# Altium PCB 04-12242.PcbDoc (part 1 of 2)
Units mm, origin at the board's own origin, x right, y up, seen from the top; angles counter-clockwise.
Board outline 90 x 78 mm, 2 copper layers (Top Layer, Bottom Layer), stack 1.57 mm thick; 64 components, 48 nets, 276 pads, 503 vias.
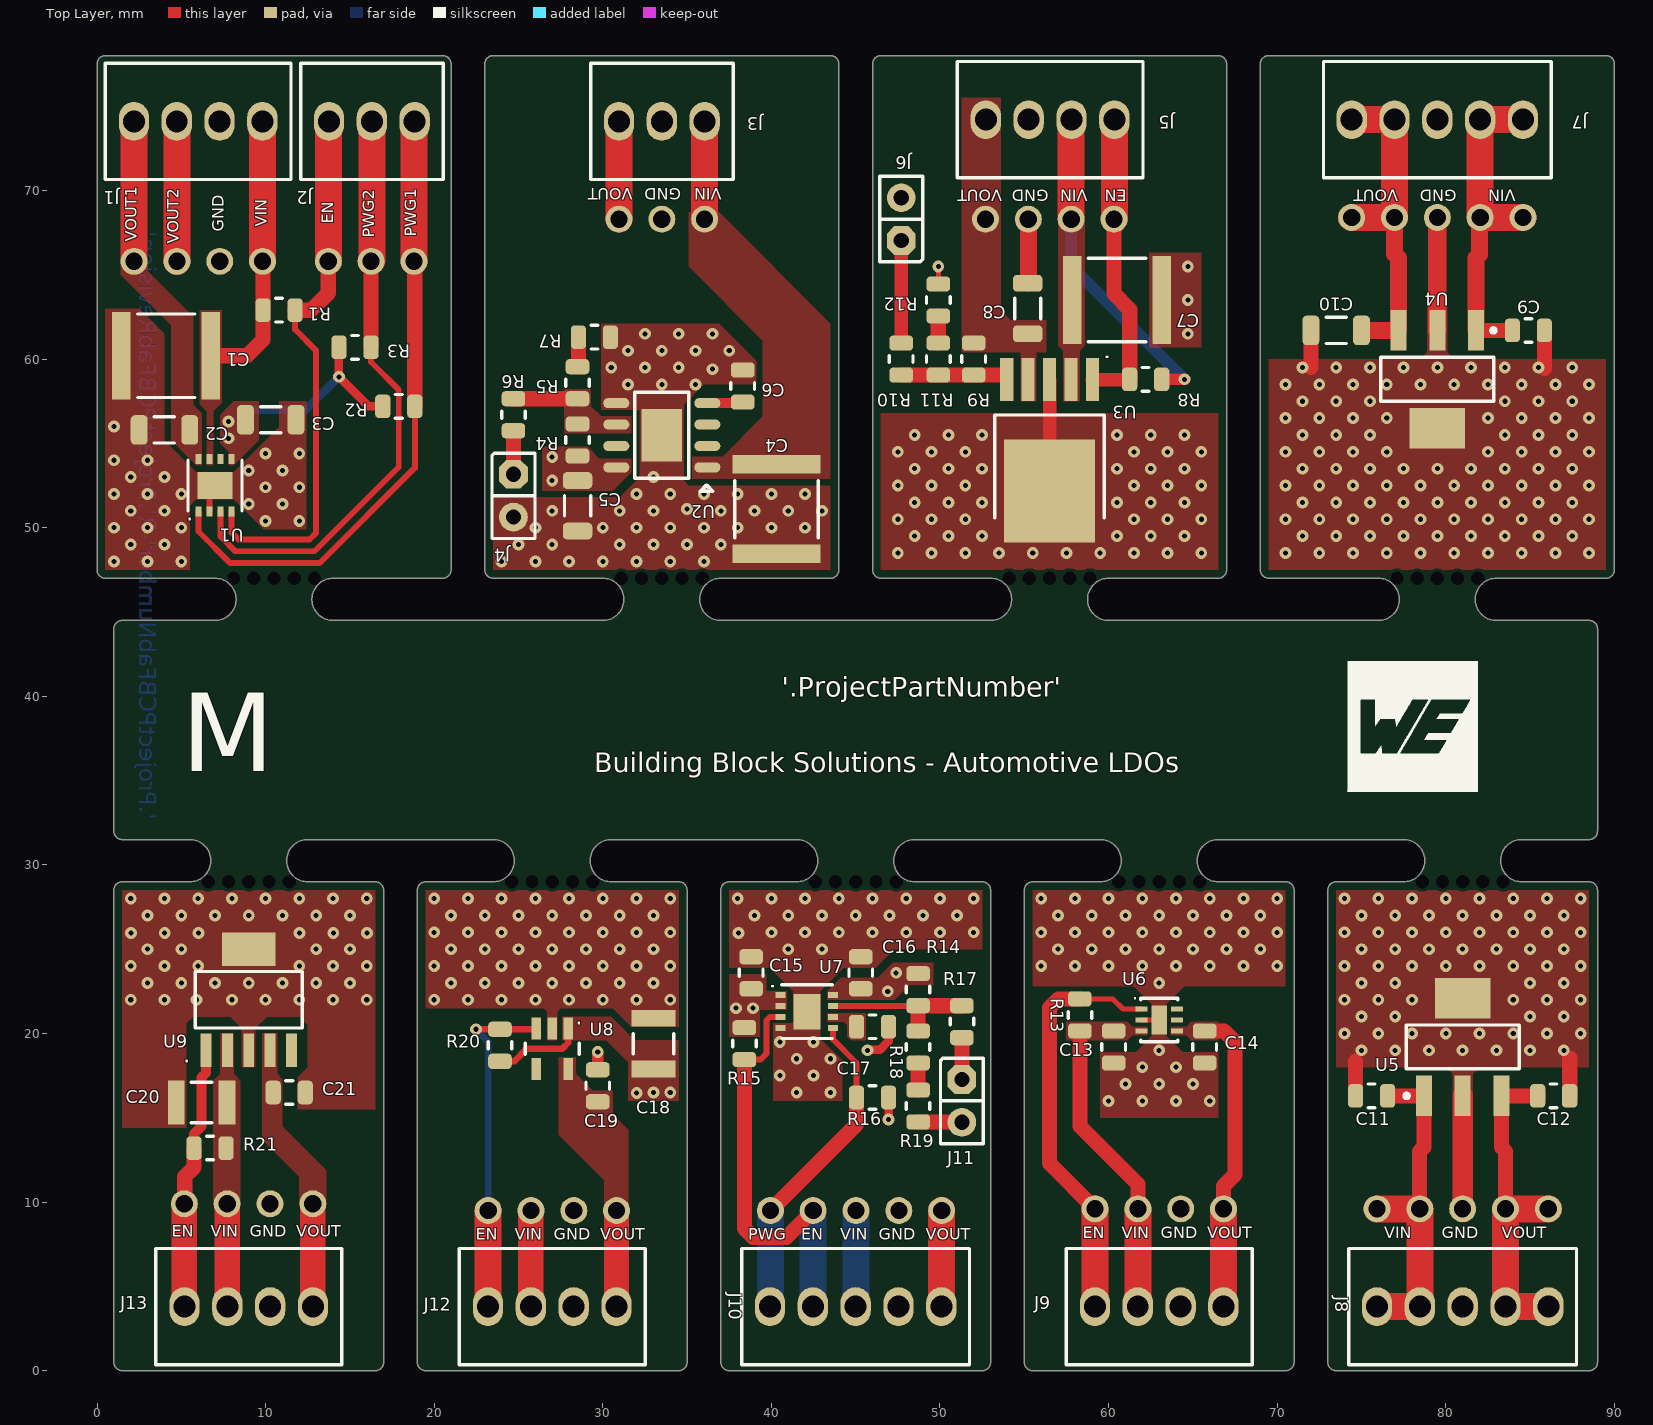
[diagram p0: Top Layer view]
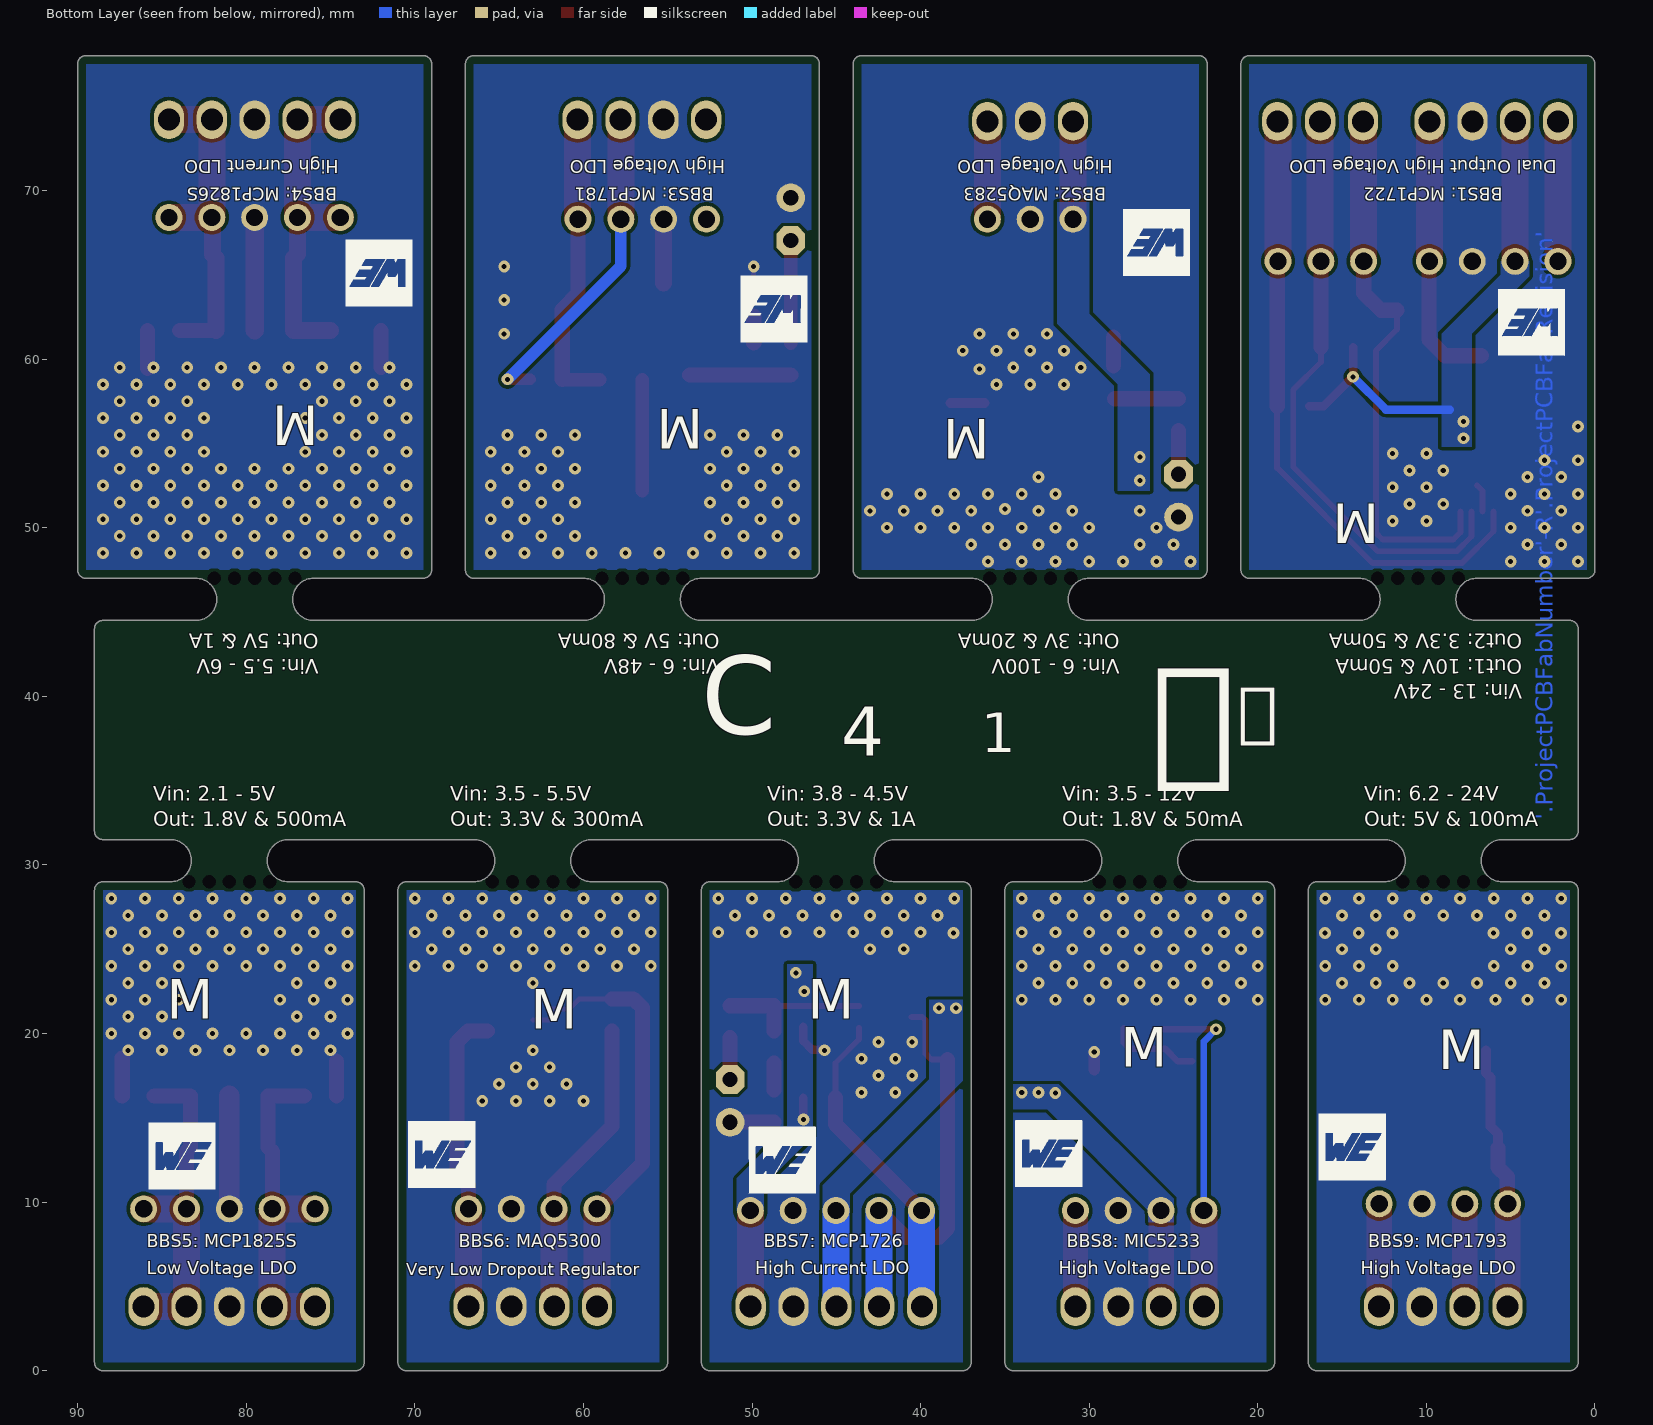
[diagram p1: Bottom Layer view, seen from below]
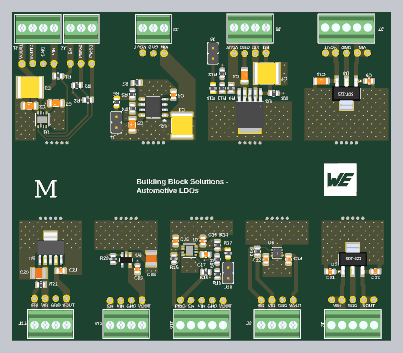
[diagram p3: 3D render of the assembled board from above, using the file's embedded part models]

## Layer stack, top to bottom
Top Solder: solder mask 0.01, Solder Resist, Dk 3.5
Top Layer: signal copper 0.035
Dielectric1: core 1.5, FR-4, Dk 4.8
Bottom Layer: signal copper 0.035
Bottom Solder: solder mask 0.01, Solder Resist, Dk 3.5

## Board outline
1.5,0 16.5,0 ccw(c16.5,0.5) 17,0.5 17,28.5 ccw(c16.5,28.5) 16.5,29 12.5,29 cw(c12.5,30.25) 12.5,31.5 23.5,31.5 cw(c23.5,30.25) 23.5,29 19.5,29 ccw(c19.5,28.5) 19,28.5 19,0.497 19,0.5 ccw(c19.5,0.5) 19.5,0 34.5,0 ccw(c34.5,0.5) 35,0.5 35,28.5 ccw(c34.5,28.5) 34.5,29 30.5,29 cw(c30.5,30.25) 30.5,31.5 41.5,31.5 cw(c41.5,30.25) 41.5,29 37.5,29 ccw(c37.5,28.5) 37,28.5 37,0.5 ccw(c37.5,0.5) 37.5,0 52.5,0 ccw(c52.5,0.5) 53,0.5 53,28.5 ccw(c52.5,28.5) 52.5,29 48.5,29 cw(c48.5,30.25) 48.5,31.5 59.5,31.5 cw(c59.5,30.25) 59.5,29 55.5,29 ccw(c55.5,28.5) 55,28.5 55,0.5 ccw(c55.5,0.5) 55.5,0 70.5,0 ccw(c70.5,0.5) 71,0.5 71,0.496 71,28.5 ccw(c70.5,28.5) 70.5,29 66.5,29 cw(c66.5,30.25) 66.5,31.5 77.5,31.5 cw(c77.5,30.25) 77.5,29 73.5,29 ccw(c73.5,28.5) 73,28.5 73,0.5 ccw(c73.5,0.5) 73.5,0 88.5,0 ccw(c88.5,0.5) 89,0.5 89,0.495 89,28.5 ccw(c88.5,28.5) 88.5,29 84.5,29 cw(c84.5,30.25) 84.5,31.5 88.5,31.5 ccw(c88.5,32) 89,32 89,44 ccw(c88.5,44) 88.5,44.5 83,44.5 cw(c83,45.75) 83,47 89.5,47 ccw(c89.5,47.5) 90,47.5 90,77.5 ccw(c89.5,77.5) 89.5,78 69.5,78 ccw(c69.5,77.5) 69,77.5 69,47.5 ccw(c69.5,47.5) 69.5,47 76,47 cw(c76,45.75) 76,44.5 60,44.5 cw(c60,45.75) 60,47 66.5,47 ccw(c66.5,47.5) 67,47.5 67,77.5 ccw(c66.5,77.5) 66.5,78 46.5,78 ccw(c46.5,77.5) 46,77.5 46,47.5 ccw(c46.5,47.5) 46.5,47 53,47 cw(c53,45.75) 53,44.5 37,44.5 cw(c37,45.75) 37,47 43.5,47 ccw(c43.5,47.5) 44,47.5 44,77.5 ccw(c43.5,77.5) 43.5,78 23.5,78 ccw(c23.5,77.5) 23,77.5 23,47.5 ccw(c23.5,47.5) 23.5,47 30,47 cw(c30,45.75) 30,44.5 14,44.5 cw(c14,45.75) 14,47 20.5,47 ccw(c20.5,47.5) 21,47.5 21,77.5 ccw(c20.5,77.5) 20.5,78 0.5,78 ccw(c0.5,77.5) 0,77.5 0,47.5 ccw(c0.5,47.5) 0.5,47 7,47 cw(c7,45.75) 7,44.5 1.5,44.5 ccw(c1.5,44) 1,44 1,32 ccw(c1.5,32) 1.5,31.5 5.5,31.5 cw(c5.5,30.25) 5.5,29 1.5,29 ccw(c1.5,28.5) 1,28.5 1,0.496 1,0.5 ccw(c1.5,0.5)

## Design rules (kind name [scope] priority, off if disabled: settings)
AcuteAngle [All] p1: minimum=9.00000000000000E+0001 checktracksonly=TRUE
BoardOutlineClearance "Ignore Title Block elements" [InNamedUnion('Title Block')] p1: gap=0 ignorepadtopadclearanceinfootprint=FALSE
BoardOutlineClearance BoardOutlineClearance_Overlay [OnLayer('Top Overlay','Bottom Overlay')] p2: gap=0.2 ignorepadtopadclearanceinfootprint=FALSE
BoardOutlineClearance [All] p3: gap=0.5 ignorepadtopadclearanceinfootprint=FALSE
Clearance "Net to Polygon 0.5mm" [InNet('your net here') vs (IsRegion)] p1: gap=0.2 ignorepadtopadclearanceinfootprint=FALSE
Clearance "Poly 0.3mm" [(IsRegion)] p2: gap=0.2 ignorepadtopadclearanceinfootprint=FALSE
Clearance [All] p3: gap=0.2 ignorepadtopadclearanceinfootprint=TRUE
ComponentClearance ComponentClearance_ignore [HasFootprint('NET_TIE_0.5mm')] p1: gap=0 collisioncheckmode=3 verticalgap=0 showdistances=FALSE
ComponentClearance [All] p2: gap=0.2 collisioncheckmode=3 verticalgap=0.2 showdistances=FALSE
DiffPairsRouting [All] p1: maxlimit=0.25 minlimit=0.25 mostfreqgap=0.25 toplayer_minwidth=0.25 toplayer_maxwidth=0.25 toplayer_prefwidth=0.25 bottomlayer_minwidth=0.25 bottomlayer_maxwidth=0.25 bottomlayer_prefwidth=0.25 maxuncoupledlength=12.7
FabricationTestPointUsage TestPointUsage [All] p1: valid=0 allowmultiple=FALSE
FabricationTestpoint Testpoint [All] p1: side=3 testpointundercomponent=TRUE minsize=1.016 maxsize=2.54 preferedsize=1.524 minholesize=0 maxholesize=1.016 preferedholesize=0.813 testpointgrid=0.025 allowsidetop=TRUE allowsidebottom=TRUE usegrid=TRUE gridtolerance=0
HoleSize [All] p1: absolutevalues=TRUE maxlimit=6 minlimit=0.25 maxpercent=80.000 minpercent=20.000
HoleToHoleClearance [All] p1: gap=0.3 allowstackedmicrovias=FALSE
MinimumAnnularRing [All] p1: minimumring=0.15
MinimumSolderMaskSliver [All] p1: minsoldermaskwidth=0.1
PasteMaskExpansion PasteMaskExpansion_DNP [IsPad AND HasCompParameterValue('Populated','DNP')] p1: expansion=-5
PasteMaskExpansion [All] p2: expansion=0
PlaneClearance PlaneClearance_pads [IsPad] p1: clearance=0.3
PlaneClearance PlaneClearance_drill [IsObjectKind('Hole')] p2: clearance=0.4
PlaneConnect PlaneConnect_full [IsVia] p1: planeconnectstyle=Direct reliefexpansion=0.5 reliefentries=4 reliefconductorwidth=0.3 reliefairgap=0.3
PlaneConnect [All] p2: planeconnectstyle=Relief reliefexpansion=0.3 reliefentries=4 reliefconductorwidth=0.25 reliefairgap=0.25
PolygonConnect PolygonConnect_0.7 [IsNamedPolygon('0.7mm') vs (InPadClass('All Pads'))] p1: connectstyle=Relief reliefconductorwidth=0.7 reliefentries=4 polygonreliefangle="90 Angle" airgapwidth=0.25
PolygonConnect PolygonConnect_0.5 [IsNamedPolygon('0.5mm') vs (InPadClass('All Pads'))] p2: connectstyle=Relief reliefconductorwidth=0.5 reliefentries=4 polygonreliefangle="90 Angle" airgapwidth=0.25
PolygonConnect PolygonConnect_full [All vs IsVia or IsNamedPolygon('full')] p3: connectstyle=Direct reliefconductorwidth=0 reliefentries=4 polygonreliefangle="90 Angle" airgapwidth=0.254
PolygonConnect [All] p4: connectstyle=Relief reliefconductorwidth=0.3 reliefentries=4 polygonreliefangle="90 Angle" airgapwidth=0.25
RoutingCorners [All] p1: cornerstyle=45-Degree minsetback=2.5 maxsetback=2.5
RoutingVias [All] p1: holewidth=0.4 width=0.8 viastyle="Through Hole" minholewidth=0.3 minwidth=0.7 maxholewidth=1.6 maxwidth=2.5
SMDToCorner [All] p1: distance=39370
ShortCircuit [IsNet] p1: allowed=FALSE
SilkToSilkClearance [All] p1: silktosilkclearance=0.15
SilkToSolderMaskClearance SilkscreenOverComponentPads [IsPad] p1: minsilkscreentomaskgap=0.2 clearancetoexposedcopper=TRUE
SolderMaskExpansion SolderMaskExpansion_Component_Via [IsComponentVia] p1: expansion=0.075 istentingtop=FALSE soldermaskfromhole=TRUE
SolderMaskExpansion [All] p2: expansion=0.1 istentingtop=FALSE
SupplyNets "Schematic Supply Nets_1" [InNet('GND_2')] p1: voltage=0.000
SupplyNets "Schematic Supply Nets_8" [InNet('GND_9')] p2: voltage=0.000
SupplyNets "Schematic Supply Nets_4" [InNet('GND_8')] p3: voltage=0.000
SupplyNets "Schematic Supply Nets_7" [InNet('GND_3')] p4: voltage=0.000
SupplyNets "Schematic Supply Nets_6" [InNet('GND_4')] p5: voltage=0.000
SupplyNets "Schematic Supply Nets_5" [InNet('GND_7')] p6: voltage=0.000
SupplyNets "Schematic Supply Nets_3" [InNet('GND_5')] p7: voltage=0.000
SupplyNets "Schematic Supply Nets_2" [InNet('GND_6')] p8: voltage=0.000
SupplyNets "Schematic Supply Nets" [InNet('GND_1')] p9: voltage=0.000
UnRoutedNet [All] p1: checkbadconnections=TRUE
ViasUnderSMD [All] p1: allowed=FALSE
Width [All] p1: maxlimit=7 minlimit=0.2 preferedwidth=0.25
15 further rules are at their usual default settings.

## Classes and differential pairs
component class MAQ5300_schematic: C13 C14 J9 R13 U6
component class MAQ5283_schematic: C4 C5 C6 J3 J4 R4 R5 R6 R7 U2
component class MCP1825S_schematic: C11 C12 J8 U5
component class MIC5233_schematic: C18 C19 J12 R20 U8
component class MCP1793_schematic: C20 C21 J13 R21 U9
component class MCP1726_schematic: C15 C16 C17 J10 J11 R14 R15 R16 R17 R18 R19 U7
component class MCP1722_schematic: C1 C2 C3 J1 J2 R1 R2 R3 U1
component class MCP1826S_schematic: C9 C10 J7 U4
component class MCP1781_schematic: C7 C8 J5 J6 R8 R9 R10 R11 R12 U3

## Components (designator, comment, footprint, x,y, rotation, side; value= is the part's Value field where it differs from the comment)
C1 "Capacitor NP" CAP_C_2220 4.1,60.2 r0 top value=4.7uF
C2 "Capacitor NP" CAP_C_1206 4,55.8 r0 top value=3.3uF
C3 "Capacitor NP" CAP_C_1206 10.3,56.4 r180 top value=3.3uF
C4 "Capacitor NP" CAP_C_2220 40.3,51.1 r90 top value=1uF
C5 "Capacitor NP" CAP_C_1206 28.5,51.3 r90 top value=10uF
C6 "Capacitor NP" CAP_C_0805 38.3,58.4 r270 top value=0.1uF
C7 "Capacitor NP" CAP_C_2220 60.5,63.5 r180 top value=4.7uF
C8 "Capacitor NP" CAP_C_1206 55.2,63 r270 top value=3.3uF
C9 "Capacitor NP" CAP_C_0805 84.9,61.7 r180 top value=1uF
C10 "Capacitor NP" CAP_C_1206 73.5,61.7 r0 top value=10uF
C11 "Capacitor NP" CAP_C_0805 75.6,16.3 r0 top value=1uF
C12 "Capacitor NP" CAP_C_0805 86.4,16.3 r180 top value=1uF
C13 "Capacitor NP" CAP_C_0805 60.3,19.2 r90 top value=1uF
C14 "Capacitor NP" CAP_C_0805 65.7,19.2 r90 top value=1uF
C15 "Capacitor NP" CAP_C_0805 38.8,23.6 r270 top value=1uF
C16 "Capacitor NP" CAP_C_0805 45.3,23.6 r270 top value=1uF
C17 "Capacitor NP" CAP_C_0805 46,20.4 r180 top value=0.1uF
C18 "Capacitor NP" CAP_C_1210 33,19.4 r270 top value=2.2uF
C19 "Capacitor NP" CAP_C_0805 29.7,16.9 r270 top value=2.2uF
C20 "Capacitor NP" CAP_C_1210 6.2,15.9 r0 top value=2.2uF
C21 "Capacitor NP" CAP_C_0805 11.4,16.5 r180 top value=2.2uF
J1 "Header 1x4" CON_TERMINAL_2.54_1x4_TH_RA_WE 6,74.1 r180 top value="TERMINAL 1x4"
J2 "Header 1x3" CON_TERMINAL_2.54_1x3_TH_RA_WE 16.3,74.1 r180 top value="TERMINAL 1x3"
J3 "Header 1x3" CON_TERMINAL_2.54_1x3_TH_RA_WE 33.5,74.1 r180 top value="TERMINAL 1x3"
J4 "Header 1x2" HDR_M_2.54_1x2 24.7,51.9 r270 top value="HDR-2.54 Male 1x2"
J5 "Header 1x4" CON_TERMINAL_2.54_1x4_TH_RA_WE 56.53,74.2 r180 top value="TERMINAL 1x4"
J6 "Header 1x2" HDR_M_2.54_1x2 47.7,68.3 r90 top value="HDR-2.54 Male 1x2"
J7 "Header 1x5" CON_TERMINAL_2.54_1x5_TH_RA_WE 79.5,74.2 r180 top value="TERMINAL 1x5"
J8 "Header 1x5" CON_TERMINAL_2.54_1x5_TH_RA_WE 81,3.8 r0 top value="TERMINAL 1x5"
J9 "Header 1x4" CON_TERMINAL_2.54_1x4_TH_RA_WE 63,3.8 r0 top value="TERMINAL 1x4"
J10 "Header 1x5" CON_TERMINAL_2.54_1x5_TH_RA_WE 45,3.8 r0 top value="TERMINAL 1x5"
J11 "Header 1x2" HDR_M_2.54_1x2 51.3,16 r270 top value="HDR-2.54 Male 1x2"
J12 "Header 1x4" CON_TERMINAL_2.54_1x4_TH_RA_WE 27,3.8 r0 top value="TERMINAL 1x4"
J13 "Header 1x4" CON_TERMINAL_2.54_1x4_TH_RA_WE 9,3.8 r0 top value="TERMINAL 1x4"
R1 "Resistor" RES_C_0805#1 10.8,62.9 r180 top value=100k
R2 "Resistor" RES_C_0805#1 17.9,57.2 r0 top value=100k
R3 "Resistor" RES_C_0805#1 15.3,60.7 r0 top value=100k
R4 "Resistor" RES_C_0805#1 28.5,55.2 r90 top value=100k
R5 "Resistor" RES_C_0805#1 28.5,58.6 r270 top value=68k
R6 "Resistor" RES_C_0805#2 24.7,56.7 r90 top value=100k
R7 "Resistor" RES_C_0805#1 29.5,61.3 r180 top value=1.3k
R8 "Resistor" RES_C_0805#1 62.2,58.8 r0 top value=100k
R9 "Resistor" RES_C_0805#1 52,60 r270 top value=100k
R10 "Resistor" RES_C_0805#2 47.7,60 r270 top value=100k
R11 "Resistor" RES_C_0805#1 49.9,60 r270 top value=1.8k
R12 "Resistor" RES_C_0805#1 49.9,63.5 r270 top value=30k
R13 "Resistor" RES_C_0805#1 58.3,21.1 r90 top value=100k
R14 "Resistor" RES_C_0805#1 48.7,22.6 r90 top value=100k
R15 "Resistor" RES_C_0805#1 38.4,19.4 r270 top value=100k
R16 "Resistor" RES_C_0805#1 46,16.2 r0 top value=100k
R17 "Resistor" RES_C_0805#2 51.3,20.7 r90 top value=100k
R18 "Resistor" RES_C_0805#1 48.7,19.2 r90 top value=13K
R19 "Resistor" RES_C_0805#1 48.7,15.7 r90 top value=1.2k
R20 "Resistor" RES_C_0805#1 23.9,19.3 r90 top value=100k
R21 "Resistor" RES_C_0805#1 6.7,13.2 r0 top value=100k
U1 "MCP1722_DFN-8_EP" DFN-8_3x3 7,52.513 r0 top value=MCP1722/3.3V/10V
U2 "MAQ5283_SOIC-8" SOIC-8_EP2.41x3.1 33.5,55.483 r180 top value=MAQ5283YME-TRVAO
U3 "MCP1781 SOT-223-5_ADJ" TO-252-5_5pins 56.5,54.6 r180 top value=MCP1781
U4 "MIC39100 SOT-223-3" SOT-223-3 79.5,58.8 r180 top value=MCP1826S/5V
U5 "MIC39100 SOT-223-3" SOT-223-3 81,19.2 r0 top value=MCP1825S/1.8V
U6 "MAQ5300 DFN-6" DFN-6_2x2_EP1.7x0.9 63,20.8 r270 top value=MAQ5300-3.3YML-TRVAO
U7 "MCP172X ADJ DFN-8" DFN-8_3x3 42.1,21.3 r270 top value=MCP1726T-ADJE/MFVAO
U8 "MIC5233 SOT-23-5" SOT-23-5 27,19.1 r180 top value=MIC5233-1.8YM5
U9 "MCP1793T_SOT-223" SOT-223-5 9,22 r0 top value=MCP1793T-5002H/DCVAO

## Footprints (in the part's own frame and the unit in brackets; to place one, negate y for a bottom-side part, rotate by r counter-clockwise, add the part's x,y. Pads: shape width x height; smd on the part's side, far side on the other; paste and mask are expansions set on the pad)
CAP_C_0805 [mm] "Chip Capacitor, 2-Leads, Body 2.0x1.3mm, IPC Medium Density"
  rrect50% 0.9x1.4 smd: 1(-0.95,0) 2(0.95,0)
  silkscreen extent -0.2,-0.7 0.2,0.7, body extent -1,-0.62 1,0.63, height 0.78
CAP_C_1206 [mm] "Chip Capacitor, 2-Leads, Body 3.2x1.6mm, IPC Medium Density"
  rrect50% 1x1.75 smd: 1(-1.5,0) 2(1.5,0)
  silkscreen extent -0.6,-0.77 0.6,0.77, body extent -1.6,-0.8 1.6,0.8, height 1
CAP_C_1210 [mm] "Chip Capacitor, 2-Leads, Body 3.2x2.5mm, IPC Medium Density"
  rect 1x2.6 smd: 1(-1.5,0) 2(1.5,0)
  silkscreen extent -0.6,-1.2 0.6,1.2, body extent -1.6,-1.25 1.6,1.25, height 0.95
CAP_C_2220 [mm] "Chip Capacitor, 2-Leads, Body 5.7x5.0mm, IPC Medium Density"
  rect 1.1x5.2 smd: 1(-2.65,0) 2(2.65,0)
  silkscreen extent -1.7,-2.47 1.7,2.48, body extent -2.85,-2.5 2.85,2.5, height 2.3
CON_TERMINAL_2.54_1x3_TH_RA_WE [mm]
  oval 1.8x2.3 hole 1.3: 1(-2.54,0) 2(0,0) 3(2.54,0)
  silkscreen extent -4.24,-3.45 4.22,3.45, body extent -4.01,-3.25 4.01,3.25, height 8.55
CON_TERMINAL_2.54_1x4_TH_RA_WE [mm]
  oval 1.8x2.3 hole 1.3: 1(-3.81,0) 2(-1.27,0) 3(1.27,0) 4(3.81,0)
  silkscreen extent -5.51,-3.45 5.51,3.45, body extent -5.28,-3.25 5.28,3.25, height 8.55
CON_TERMINAL_2.54_1x5_TH_RA_WE [mm] "CON_TERMINAL_2.54_1x5_TH_RA_WE"
  oval 1.8x2.3 hole 1.3: 1(-5.08,0) 2(-2.54,0) 3(0,0) 4(2.54,0) 5(5.08,0)
  silkscreen extent -6.75,-3.45 6.75,3.45, body extent -6.55,-3.25 6.55,3.25, height 8.55
DFN-6_2x2_EP1.7x0.9 [mm] "DFN, 6-Leads, Body 2.0x2.0mm (max), Pitch 0.65"
  rect 0.3x0.7 smd: 1(-0.65,-1.05) 2(0,-1.05) 3(0.65,-1.05) 4(0.65,1.05) 5(0,1.05) 6(-0.65,1.05)
  rect 1.7x0.9 smd mask+0.05: 7(0,0)
  silkscreen extent -1.3,-1.1 1.3,1.1, body extent -1,-1 1,1, height 0.75
DFN-8_3x3 [mm] "DFN, 8-Leads, Body 3.0x3.0mm (max), Pitch 0.65mm, IPC Medium Density"
  rect 0.35x0.6 smd: 1(-0.975,-1.55) 2(-0.325,-1.55) 3(0.325,-1.55) 4(0.975,-1.55) 5(0.975,1.55) 6(0.325,1.55) 7(-0.325,1.55) 8(-0.975,1.55)
  rect 2.1x1.6 smd: 9(0,0)
  silkscreen extent -1.6,-1.5 1.6,1.5, body extent -1.5,-1.5 1.5,1.5, height 0.6
HDR_M_2.54_1x2 [mm] "Header Male Vertical 2 Way 2.54mm Pitch"
  oct 1.7x1.7 hole 0.9: 1(-1.27,0)
  round 1.7 hole 0.9: 2(1.27,0)
  silkscreen extent -2.52,-1.27 2.54,1.28, body extent -2.54,-1.27 2.54,1.27, height 5.94
RES_C_0805#1 [mm] "Chip Resistor, 2-Leads, Body 2.0x1.3mm, IPC Medium Density"
  rrect50% 0.9x1.4 smd: 1(-0.95,0) 2(0.95,0)
  silkscreen extent -0.2,-0.7 0.2,0.7, body extent -1,-0.63 1,0.63, height 0.78
RES_C_0805#2 [mm] "Chip Resistor, 2-Leads, Body 2.0x1.3mm, IPC Medium Density"
  rrect50% 0.9x1.4 smd paste-1: 1(-0.95,0) 2(0.95,0)
  silkscreen extent -0.2,-0.7 0.2,0.7, body extent -1,-0.63 1,0.63, height 0.78
SOIC-8_EP2.41x3.1 [mm] "SOIC, 8-Leads, Overall 4.9x6mm, Pitch 1.27mm, Exposed Pad 2.41x3.1mm, IPC Medium Density"
  oval 1.55x0.6 smd: 1(-2.7,1.905) 2(-2.7,0.635) 3(-2.7,-0.635) 4(-2.7,-1.905) 5(2.7,-1.905) 6(2.7,-0.635) 7(2.7,0.635) 8(2.7,1.905)
  rect 2.41x3.1 smd: 9(0,0)
  silkscreen extent -3.03,-2.55 1.6,3.32, body extent -3.01,-2.5 3.01,2.5, height 1.75
SOT-23-5 [mm] "SOT-23-5"
  rect 0.55x1.3 smd: 1(-0.95,-1.2) 2(0,-1.2) 3(0.95,-1.2) 4(0.95,1.2) 5(-0.95,1.2)
  silkscreen extent -1.6,-0.33 1.6,0.33, body extent -1.5,-1.25 1.5,1.25, height 1.08
SOT-223-3 [mm] "SOT223-3, 4-Leads, Body 6.7x7.3mm (max), Pitch 2.30mm, IPC Medium Density"
  rect 0.95x2.4 smd: 1(-2.3,-2.9) 2(0,-2.9) 3(2.3,-2.9)
  rect 3.3x2.4 smd: 2(0,2.9)
  silkscreen extent -3.45,-3.02 3.35,1.3, body extent -3.3,-3.55 3.4,3.65, height 1.85
SOT-223-5 [mm] "SOT-223-5, 5-Leads + thermal connected to pin 3, Body 6.5x7.26mm (max), Pitch 1.27mm H=1.65mm"
  rect 0.65x2 smd: 1(-2.54,-3) 2(-1.27,-3) 3(0,-3) 4(1.27,-3) 5(2.54,-3)
  rect 3.2x2 smd: 6(0,3)
  silkscreen extent -3.17,-1.68 3.17,1.68, body extent -3.27,-3.63 3.28,3.63, height 1.8
TO-252-5_5pins [mm]
  rect 0.78x2.56 smd: 1(-2.54,-4.18) 2(-1.27,-4.18) 3(0,-4.18) 4(1.27,-4.18) 5(2.54,-4.18)
  rect 5.4x6.11 smd paste-4: 6(0,2.41)
  silkscreen extent -3.25,-2.08 3.25,4.02, body extent -3.3,-4.96 3.3,5.25, height 2.39

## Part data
C1 C7: library part CAP0569, Manufacturer 1="Wuerth Elektronik", Manufacturer 2=Murata, Manufacturer Part Number 1=885012214003, Manufacturer Part Number 2=GRM55ER72A475KA01L, Operating Temperature="-55C to +125C", Package=2220, Supplier Part Number 1=732-885012214003TR-ND, Temperature Coefficient=X7R, Tolerance=10%, Voltage=100V
C2 C3 C8: library part CAP3265, Manufacturer 1="Wuerth Elektronik", Manufacturer Part Number 1=885012208067, Operating Temperature="-55C to +125C", Package=1206, Supplier Part Number 1=732-7572-2-ND, Temperature Coefficient=X7R, Tolerance=10%, Voltage=25V
C4: library part CAP3266, Manufacturer 1="Wuerth Elektronik", Manufacturer Part Number 1=885342214002, Operating Temperature="-55C to +125C", Package=2220, Supplier Part Number 1=732-885342214002TR-ND, Temperature Coefficient=X7R, Tolerance=10%, Voltage=250V
C5 C10: library part CAP2272, Manufacturer 1="Würth Elektronik", Manufacturer Part Number 1=885012208069, Operating Temperature="-55C to +125C", Package=1206, Supplier Part Number 1=732-7574-1-ND, Temperature Coefficient=X7R, Tolerance=10%, Voltage=25V
C6 C17: library part CAP3267, Manufacturer 1="Wuerth Elektronik", Manufacturer Part Number 1=885012207072, Operating Temperature="-55C to +125C", Package=0805, Supplier Part Number 1=732-8061-2-ND, Temperature Coefficient=X7R, Tolerance=10%, Voltage=25V
C9 C11 C12 C13 C14 C15 C16: library part CAP2456, Manufacturer 1="Wurth Electronics", Manufacturer Part Number 1=885012207078, Operating Temperature="-55C to +125C", Package=0805, Supplier Part Number 1=710-885012207078, Temperature Coefficient=X7R, Tolerance=10%, Voltage=25V
C18 C20: library part CAP2455, Manufacturer 1=Murata, Manufacturer 2="Wuerth Elektronik", Manufacturer Part Number 1=GRM32ER72A225KA35K, Manufacturer Part Number 2=885012209071, Operating Temperature="-55C to +125C", Package=1210, Supplier Part Number 1=490-6545-2-ND, Temperature Coefficient=X7R, Tolerance=10%, Voltage=100V
C19 C21: library part CAP2292, Manufacturer 1="Würth Elektronik", Manufacturer Part Number 1=885012207079, Operating Temperature="-55C to 125C", Package=0805, Supplier Part Number 1=732-7673-1-ND, Temperature Coefficient=X7R, Tolerance=10%, Voltage=25V
J1 J5 J9 J12 J13: library part CON3130, Current=6A, Manufacturer 1="Wuerth Elektronik", Manufacturer Part Number 1=691210910004, Supplier Part Number 1=732-691210910004-ND, Voltage=150V
J2 J3: library part CON3164, Current=6A, Manufacturer 1="Wuerth Elektronik", Manufacturer Part Number 1=691210910003, Supplier Part Number 1=732-691210910003-ND, Voltage=150V
J4 J6 J11: library part CON1108, Manufacturer 1="Amphenol ICC (FCI)", Manufacturer 4=Samtec, Manufacturer 5="Sullins Connector Solutions", Manufacturer 6="Wuerth Elektronik", Manufacturer 9="Shanghai NS-TECH", Manufacturer Part Number 1=68001-202HLF, Manufacturer Part Number 2=68000-202HLF, Manufacturer Part Number 3=77311-118-02LF, Manufacturer Part Number 4=TSW-102-07-G-S, Manufacturer Part Number 5=PBC02SAAN, Manufacturer Part Number 6=61300211121, Manufacturer Part Number 7=TSW-102-07-F-S, Manufacturer Part Number 8=TSW-102-07-S-S, Manufacturer Part Number 9=NS-201-SH0100-1*2, Supplier Part Number 1=609-3469-ND
J7 J8 J10: library part CON3131, Current=6A, Manufacturer 1="Wuerth Elektronik", Manufacturer Part Number 1=691210910005, Supplier Part Number 1=732-691210910005-ND, Voltage=150V
R1 R2 R3 R4 R6 R8 R9 R10 R13 R14 R15 R16 R17 R21: library part RES3525, Manufacturer 1="KOA Speer", Manufacturer Part Number 1=RK73H2ATTD1003F, Operating Temperature="-55C to +155C", Package=0805, Power=1/4W, Supplier Part Number 1=2019-RK73H2ATTD1003FTR-ND, Temperature Coefficient=100ppm/C, Tolerance=1%
R5: library part RES2951, Manufacturer 1="TE Connectivity Passive Product", Manufacturer 2="Stackpole Electronics Inc", Manufacturer 3=Yageo, Manufacturer Part Number 1=CRGCQ0805F68K, Manufacturer Part Number 2=RMCF0805FT68K0, Manufacturer Part Number 3=RC0805FR-0768KL, Operating Temperature="-55C to +155C", Package=0805, Power=1/8W, Supplier Part Number 1=A129771TR-ND, Temperature Coefficient=100ppm/C, Tolerance=1%, Voltage=150V
R7: library part RES1416, Manufacturer 1=Yageo, Manufacturer Part Number 1=RC0805FR-071K3L, Operating Temperature="-55C to +155C", Package=0805, Power=1/8W, Supplier Part Number 1=311-1.30KCRCT-ND, Temperature Coefficient=100ppm/C, Tolerance=1%, Voltage=150V
R11: library part RSMT0599, Manufacturer 1=Panasonic, Manufacturer Part Number 1=ERJ-6ENF1801V, Operating Temperature="-55C to +155C", Package=0805, Power=1/8W, Supplier Part Number 1=P1.80KCCT-ND, Temperature Coefficient=100ppm/C, Tolerance=1%, Voltage=150V
R12: library part RSMT0525, Manufacturer 1=Panasonic, Manufacturer 2=Yageo, Manufacturer Part Number 1=ERJ-6ENF3002V, Manufacturer Part Number 2=RC0805FR-0730KL, Operating Temperature="-55C to +155C", Package=0805, Power=1/8W, Supplier Part Number 1=P30.0KCCT-ND, Temperature Coefficient=100ppm/C, Tolerance=1%, Voltage=150V
R18: library part RES2889, Manufacturer 1="Panasonic Electronic Components", Manufacturer Part Number 1=ERJ-U06F1302V, Operating Temperature="-55°C to 155°C", Package=0805, Power=1/8W, Supplier Part Number 1=10-ERJ-U06F1302VTR-ND, Temperature Coefficient=±100ppm/°C, Tolerance=1%
R19: library part RSMT0237, Manufacturer 1=Yageo, Manufacturer Part Number 1=RC0805FR-071K2L, Operating Temperature="-55C to +155C", Package=0805, Power=1/8W, Supplier Part Number 1=311-1.20KCRCT-ND, Temperature Coefficient=100ppm/C, Tolerance=1%, Voltage=150V
R20: library part RES3532, Manufacturer 1="Wuerth Elektronik", Manufacturer Part Number 1=560112120013, Operating Temperature="-55C to +155C", Package=0805, Power=1/4W, Supplier Part Number 1=710-560112120013, Temperature Coefficient=100ppm/C, Tolerance=1%
U1: library part IC3069, "LDO", Manufacturer 1="Microchip Technology", Manufacturer Part Number 1=MCP1722-3310H/Q8BVAO, Operating Temperature="-40C to +150C"
U2: library part IC3036, Manufacturer 1="Microchip Technology", Manufacturer Part Number 1=MAQ5283YME-TRVAO, Manufacturer Part Number 2=MAQ5283YME-VAO, Operating Temperature="-40C to +125C"
U3: library part IC2880, "LDO", Manufacturer 1="Microchip Technology", Manufacturer Part Number 1=MCP1781-ADJH/9EAVAO
U4: library part IC3072, "LDO", Manufacturer 1="Microchip Technology", Manufacturer Part Number 1=MCP1826S-5002E/DBVAO, Operating Temperature="-40C to +125C"
U5: library part IC3079, "LDO", Manufacturer 1="Microchip Technology", Manufacturer Part Number 1=MCP1825S-1802E/DBVAO, Operating Temperature="-40C to +125C"
U6: library part IC3040, "LDO", Manufacturer 1="Microchip Technology", Manufacturer Part Number 1=MAQ5300-3.3YML-TRVAO
U7: library part IC3039, "LDO ADJ", Manufacturer 1="Microchip Technology", Manufacturer Part Number 1=MCP1726T-ADJE/MFVAO, Operating Temperature="-40C to +125C"
U8: library part IC3071, Manufacturer 1="Microchip Technology", Manufacturer Part Number 1=MIC5233-1.8YM5-TRVAO, Operating Temperature="-40C to +125C"
U9: library part IC3037, Manufacturer 1="Microchip Technology", Manufacturer Part Number 1=MCP1793T-5002H/DCVAO, Operating Temperature="-40C to +150C"

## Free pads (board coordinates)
  round 0 hole 0.787: 1(6.6,29) 1(7.8,29) 1(8.1,47) 1(9,29) 1(9.3,47) 1(10.2,29) 1(10.5,47) 1(11.4,29) 1(11.7,47) 1(12.9,47) 1(24.6,29) 1(25.8,29) 1(27,29) 1(28.2,29) 1(29.4,29) 1(31.1,47) 1(32.3,47) 1(33.5,47) 1(34.7,47) 1(35.9,47) 1(42.6,29) 1(43.8,29) 1(45,29) 1(46.2,29) 1(47.4,29) 1(54.1,47) 1(55.3,47) 1(56.5,47) 1(57.7,47) 1(58.9,47) 1(60.6,29) 1(61.8,29) 1(63,29) 1(64.2,29) 1(65.4,29) 1(77.1,47) 1(78.3,47) 1(78.6,29) 1(79.5,47) 1(79.8,29) 1(80.7,47) 1(81,29) 1(81.9,47) 1(82.2,29) 1(83.4,29)
  round 1.6 hole 1.02: 7(2.2,65.8) 7(12.8,9.9) 7(13.72,65.8) 7(16.26,65.8) 7(18.8,65.8) 7(30.82,9.5) 7(30.96,68.3) 7(33.5,68.3) 7(36.04,68.3) 7(50.1,9.5) 7(52.7,68.3) 7(66.82,9.6) 7(74.42,68.4) 7(76.96,68.4) 7(83.54,9.6) 7(84.58,68.4) 8(4.74,65.8) 8(10.26,9.9) 8(28.28,9.5) 8(47.56,9.5) 8(55.24,68.3) 8(64.28,9.6) 8(79.5,68.4) 8(81,9.6) 9(7.28,65.8) 9(7.72,9.9) 9(25.74,9.5) 9(45.02,9.5) 9(57.78,68.3) 9(61.74,9.6) 9(75.92,9.6) 9(78.46,9.6) 9(82.04,68.4) 9(86.08,9.6) 10(5.18,9.9) 10(9.82,65.8) 10(23.2,9.5) 10(39.94,9.5) 10(42.48,9.5) 10(59.2,9.6) 10(60.32,68.3)

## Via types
v1: diameter 0.7, hole 0.3, Top Layer to Bottom Layer, 503 vias

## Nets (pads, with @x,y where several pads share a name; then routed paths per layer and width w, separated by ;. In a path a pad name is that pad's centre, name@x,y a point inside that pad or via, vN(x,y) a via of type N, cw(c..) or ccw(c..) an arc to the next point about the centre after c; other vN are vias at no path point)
ADJ_2: R4.2 R5.2 R6.2 U2.6 | length 3.8
  Top Layer w0.9: R6.2@24.7,57.65 R5.2@28.5,57.65
ADJ_3: R9.2 R10.2 R11.2 U3.5 | length 6
  Top Layer w0.9: R10.2@47.7,59.05 R11.2@49.9,59.05 R9.2@52,59.05 U3.5@53.69,59.05
ADJ_6: R14.1 R17.2 R18.2 U7.7 | length 9.2
  Top Layer w0.35: U7.7@43.65,21.625 48.675,21.625 R14.1@48.7,21.65
  Top Layer w0.9: R18.2@48.7,20.15 R14.1@48.7,21.65 R17.2@51.3,21.65
GND_1: C1.1 C2.1 C3.1 J1.2 pad.9@7.28,65.8 U1.2 U1.9 | length 1.7
  Top Layer w0.35: U1.2@6.675,50.963 6.675,52.188 U1.9@7,52.513
  other v1: 1,48 3,48 5,48 2,49 4,49 1,50 3,50 5,50 10,50.4 12,50.4 2,51 4,51 9,51.4 11,51.4 1,52 3,52 5,52 10,52.4 12,52.4 2,53 4,53 9,53.4 11,53.4 1,54 3,54 10,54.4 12,54.4 1,56
GND_2: C4.1 C5.1 C6.1 J3.2 J4.2 pad.7@33.5,68.3 R7.1 U2.5 U2.9
  other v1: 24,48 26,48 28,48 30,48 32,48 34,48 36,48 25,49 27,49 31,49 33,49 35,49 37,49 26,50 30,50 32,50 34,50 36,50 38,50 40,50 42,50 27,51 31,51 33,51 37,51 39,51 41,51 43,51 35,51.1 32,52 34,52 36,52 38,52 40,52 42,52 33,53 31.5,58.5 33.5,58.5 35.5,58.5 36.5,59.4 30.5,59.5 32.5,59.5 34.5,59.5 31.5,60.5 33.5,60.5 35.5,60.5 37.5,60.5 32.5,61.5 34.5,61.5 36.5,61.5
GND_3: C7.1 C8.1 J5.3 J6.2 pad.8@55.24,68.3 R12.1 U3.3 U3.6 | length 11.4
  Top Layer w0.3: R12.1@49.9,64.45 v1(49.9,65.5)
  Top Layer w0.8: U3.6@56.5,52.19 U3.3@56.5,58.78
  Top Layer w1: C8.1@55.24,64.5 pad.8@55.24,68.3
  other v1: 47.5,48.5 49.5,48.5 51.5,48.5 53.5,48.5 55.5,48.5 57.5,48.5 59.5,48.5 61.5,48.5 63.5,48.5 65.5,48.5 48.5,49.5 50.5,49.5 52.5,49.5 60.5,49.5 62.5,49.5 64.5,49.5 47.5,50.5 49.5,50.5 51.5,50.5 61.5,50.5 63.5,50.5 65.5,50.5 48.5,51.5 50.5,51.5 52.5,51.5 60.5,51.5 62.5,51.5 64.5,51.5 47.5,52.5 49.5,52.5 51.5,52.5 61.5,52.5 63.5,52.5 65.5,52.5 48.5,53.5 50.5,53.5 52.5,53.5 60.5,53.5 62.5,53.5 64.5,53.5 47.5,54.5 49.5,54.5 51.5,54.5 61.5,54.5 63.5,54.5 65.5,54.5 48.5,55.5 50.5,55.5 52.5,55.5 60.5,55.5 62.5,55.5 64.5,55.5 64.7,61.5 64.7,63.5 64.7,65.5
GND_4: C20.1 C21.1 J13.3 pad.8@10.26,9.9 U9.3 U9.6
  other v1: 2,22 4,22 5.9,22 8,22 10,22 12,22 14,22 16,22 3,23 5,23 7,23 9,23 11,23 13,23 15,23 2,24 4,24 6,24 12,24 14,24 16,24 3,25 5,25 13,25 15,25 2.015,25.967 4.015,25.967 6.015,25.967 12.015,25.967 14.015,25.967 16.015,25.967 3,27 5,27 7,27 9,27 11,27 13,27 15,27 2,28 4,28 6,28 8,28 10,28 12,28 14,28 16,28
GND_5: C18.1 C19.1 J12.3 pad.8@28.28,9.5 U8.2 | length 1.1
  Top Layer w0.7: C19.1@29.7,17.85 v1(29.7,18.9)
  other v1: 20,22 22,22 24,22 26,22 28,22 30,22 32,22 34,22 21,23 23,23 25,23 27,23 29,23 31,23 33,23 20,24 22,24 24,24 26,24 28,24 30,24 32,24 34,24 21,25 23,25 25,25 27,25 29,25 31,25 33,25 20,26 22,26 24,26 26,26 28,26 30,26 32,26 34,26 21,27 23,27 25,27 27,27 29,27 31,27 33,27 20,28 22,28 24,28 26,28 28,28 30,28 32,28 34,28
GND_6: C15.1 C16.1 C17.1 J10.4 J11.2 pad.8@47.56,9.5 R19.1 U7.4 U7.9 | length 4.9
  Top Layer w0.5: v1(45.7,19) 45.738,19.038 46.438,19.038 46.95,19.55 C17.1@46.95,20.4
  Top Layer w0.9: R19.1@48.7,14.75 51.28,14.75 J11.2@51.3,14.73
  other v1: 41.5,16.5 43.5,16.5 40.5,17.5 42.5,17.5 41.5,18.5 43.5,18.5 40.5,19.5 42.5,19.5 41,25 43,25 38.044,25.961 40,26 42,26 44,26 46,26 48,26 50,26 52,26 39,27 41,27 43,27 45,27 47,27 49,27 51,27 38,28 40,28 42,28 44,28 46,28 48,28 50,28 52,28
GND_7: C13.1 C14.1 J9.3 pad.8@64.28,9.6 U6.2 U6.7 | length 1.1
  Top Layer w0.3: U6.2@61.95,20.8 U6.7@63,20.8
  other v1: 60,16 62,16 64,16 66,16 61,17 63,17 65,17 62,18 64,18 63,19 63,23 56,24 58,24 60,24 62,24 64,24 66,24 68,24 70,24 57,25 59,25 61,25 63,25 65,25 67,25 69,25 56,26 58,26 60,26 62,26 64,26 66,26 68,26 70,26 57,27 59,27 61,27 63,27 65,27 67,27 69,27 56,28 58,28 60,28 62,28 64,28 66,28 68,28 70,28
GND_8: C11.1 C12.1 J8.3 pad.8@81,9.6 U5.2 | length 11
  Top Layer w0.9: C11.1@74.65,16.3 74.65,18.35 ; C12.1@87.35,16.3 87.35,18.55
  Top Layer w1.2: pad.8@81,9.6 U5.2@81,16.3
  other v1: 75,19 77,19 79,19 81,19 83,19 85,19 87,19 74,20 76,20 78,20 80,20 82,20 84,20 86,20 88,20 75,21 77,21 85,21 87,21 74,22 76,22 78,22 84,22 86,22 88,22 75,23 77,23 85,23 87,23 74,24 76,24 78,24 80,24 82,24 84,24 86,24 88,24 75,25 77,25 79,25 81,25 83,25 85,25 87,25 74,26 76,26 78,26 80,26 82,26 84,26 86,26 88,26 75,27 77,27 79,27 81,27 83,27 85,27 87,27 74,28 76,28 78,28 80,28 82,28 84,28 86,28 88,28
GND_9: C9.1 C10.1 J7.3 pad.8@79.5,68.4 U4.2 | length 11.1
  Top Layer w0.9: 72,59.5 C10.1@72,61.7 ; 85.85,59.45 C9.1@85.85,61.7
  Top Layer w1.1: U4.2@79.5,61.7 pad.8@79.5,68.4
  other v1: 70.5,48.5 72.5,48.5 74.5,48.5 76.5,48.5 78.5,48.5 80.5,48.5 82.5,48.5 84.5,48.5 86.5,48.5 88.5,48.5 71.5,49.5 73.5,49.5 75.5,49.5 77.5,49.5 79.5,49.5 81.5,49.5 83.5,49.5 85.5,49.5 87.5,49.5 70.5,50.5 72.5,50.5 74.5,50.5 76.5,50.5 78.5,50.5 80.5,50.5 82.5,50.5 84.5,50.5 86.5,50.5 88.5,50.5 71.5,51.5 73.5,51.5 75.5,51.5 77.5,51.5 79.5,51.5 81.5,51.5 83.5,51.5 85.5,51.5 87.5,51.5 70.5,52.5 72.5,52.5 74.5,52.5 76.5,52.5 78.5,52.5 80.5,52.5 82.5,52.5 84.5,52.5 86.5,52.5 88.5,52.5 71.5,53.5 73.5,53.5 75.5,53.5 77.5,53.5 79.5,53.5 81.5,53.5 83.5,53.5 85.5,53.5 87.5,53.5 70.5,54.5 72.5,54.5 74.5,54.5 76.5,54.5 82.5,54.5 84.5,54.5 86.5,54.5 88.5,54.5 71.5,55.5 73.5,55.5 75.5,55.5 83.5,55.5 85.5,55.5 87.5,55.5 70.5,56.5 72.5,56.5 74.5,56.5 76.5,56.5 82.5,56.5 84.5,56.5 86.5,56.5 88.5,56.5 71.5,57.5 73.5,57.5 75.5,57.5 83.5,57.5 85.5,57.5 87.5,57.5 70.5,58.5 72.5,58.5 74.5,58.5 76.5,58.5 78.5,58.5 80.5,58.5 82.5,58.5 84.5,58.5 86.5,58.5 88.5,58.5 71.5,59.5 73.5,59.5 75.5,59.5 77.5,59.5 79.5,59.5 81.5,59.5 83.5,59.5 85.5,59.5 87.5,59.5
NetC6_2: C6.2 U2.4 | length 2
  Top Layer w0.6: U2.4@36.2,57.388 C6.2@38.238,57.388
NetC17_2: C17.2 U7.6
NetJ4_1: J4.1 R6.1 | length 2.6
  Top Layer w0.9: J4.1@24.7,53.17 R6.1@24.7,55.75
NetJ6_1: J6.1 R10.1 | length 6.1
  Top Layer w0.8: R10.1@47.7,60.95 J6.1@47.7,67.03
NetJ11_1: J11.1 R17.1 | length 2.5
  Top Layer w0.9: J11.1@51.3,17.27 R17.1@51.3,19.75
NetR5_1: R5.1 R7.2 | length 1.7
  Top Layer w0.9: R5.1@28.55,59.6 R7.2@28.55,61.3
NetR11_1: R11.1 R12.2 | length 1.6
  Top Layer w0.9: R11.1@49.9,60.95 R12.2@49.9,62.55
NetR18_1: R18.1 R19.2 | length 1.6
  Top Layer w0.9: R19.2@48.7,16.65 R18.1@48.7,18.25
nSHDN_1: J2.3 pad.7@13.72,65.8 R1.1 U1.4 | length 33
  Top Layer w0.35: U1.4@7.975,50.963 7.975,49.725 8.4,49.3 12.6,49.3 13,49.7 13,60.5 11.75,61.75 R1.1@11.75,62.9
  Top Layer w0.9: R1.1@11.75,62.9 12.7,62.9 13.72,63.92 pad.7@13.72,65.8
  Top Layer w1.6: pad.7@13.72,65.8 13.72,74.019 13.722,74.02 13.722,74.162 J2.3@13.76,74.2
nSHDN_3: J5.1 pad.10@60.32,68.3 R8.1 U3.1 | length 18
  Top Layer w0.8: U3.1@59.04,58.78 61.23,58.78 R8.1@61.25,58.8
  Top Layer w0.9: pad.10@60.32,68.3 60.32,63.88 61.25,62.95 R8.1@61.25,58.8
  Top Layer w1.6: pad.10@60.34,68.347 J5.1@60.34,74.2
nSHDN_4: J13.1 pad.10@5.18,9.9 R21.1 U9.1 | length 15.7
  Top Layer w0.6: R21.1@5.75,13.2 5.75,14.049 6.2,14.499 6.2,17.4 6.46,17.66 U9.1@6.46,19
  Top Layer w0.9: J13.1@5.18,3.81 J13.1@5.19,3.8 ; pad.10@5.18,9.9 5.2,9.92 5.2,11.5 5.75,12.05 R21.1@5.75,13.2
  Top Layer w1.5: J13.1@5.18,3.81 pad.10@5.18,9.9
nSHDN_5: J12.1 pad.10@23.2,9.5 R20.2 U8.3 | length 20.4
  Top Layer w0.4: v1(22.472,20.25) R20.2@23.9,20.25 U8.3@26.1,20.25
  Top Layer w1.6: J12.1@23.19,3.8 23.19,9.49 pad.10@23.2,9.5
  Bottom Layer w0.4: v1(22.472,20.25) 23.2,19.522 pad.10@23.2,9.5
nSHDN_6: J10.2 pad.10@42.48,9.5 R15.2 U7.3 | length 25
  Top Layer w0.35: R15.2@38.4,18.45 39.35,18.45 39.7,18.8 39.7,20.77 39.905,20.975 U7.3@40.55,20.975
  Top Layer w0.9: R15.2@38.4,18.45 38.4,8.427 38.927,7.9 40.88,7.9 pad.10@42.48,9.5
  Top Layer w1.6: J10.2@42.46,3.8 J10.2@42.48,3.82
  Bottom Layer w1.6: J10.2@42.48,3.82 pad.10@42.48,9.5
nSHDN_7: J9.1 pad.10@59.2,9.6 R13.2 U6.1 | length 24.8
  Top Layer w0.3: R13.2@58.3,22.05 60.25,22.05 60.85,21.45 U6.1@61.95,21.45
  Top Layer w0.9: R13.2@58.3,22.05 57.027,22.05 56.5,21.523 56.5,12.3 pad.10@59.2,9.6
  Top Layer w1.6: J9.1@59.19,3.8 59.2,3.81 pad.10@59.2,9.6
PWG1_1: J2.1 pad.7@18.8,65.8 R2.2 U1.1 | length 37.8
  Top Layer w0.35: U1.1@6.025,50.963 6.025,49.775 7.9,47.9 13.2,47.9 18.85,53.55 R2.2@18.85,57.2
  Top Layer w0.9: pad.7@18.8,65.8 18.85,65.75 R2.2@18.85,57.2
  Top Layer w1.6: pad.7@18.8,65.8 18.8,74.019 18.802,74.02 18.802,74.162 J2.1@18.84,74.2
PWG2_1: J2.2 pad.7@16.26,65.8 R3.2 U1.3 | length 35.7
  Top Layer w0.35: U1.3@7.325,50.963 7.325,49.475 8.2,48.6 12.9,48.6 17.9,53.6 17.9,58.177 16.25,59.827 R3.2@16.25,60.7
  Top Layer w0.9: R3.2@16.25,60.7 16.25,65.79 pad.7@16.26,65.8
  Top Layer w1.6: pad.7@16.26,65.8 16.3,65.84 J2.2@16.3,74.1
PWG_6: J10.1 pad.10@39.94,9.5 R16.1 U7.5 | length 19.2
  Top Layer w0.35: U7.5@43.65,20.325 43.65,19.65 45.05,18.25 R16.1@45.05,16.2
  Top Layer w0.9: pad.10@39.94,9.5 45.05,14.61 R16.1@45.05,16.2
  Top Layer w1.6: J10.1@39.92,3.8 J10.1@39.94,3.82
  Bottom Layer w1.6: J10.1@39.94,3.82 pad.10@39.94,9.5
VIN_1: C1.2 J1.1 pad.10@9.82,65.8 R1.2 U1.7 | length 16.4
  Top Layer w0.9: C1.2@6.75,60.2 8.9,60.2 9.85,61.15 R1.2@9.85,62.9 9.85,65.77 pad.10@9.82,65.8
  Top Layer w1.6: pad.10@9.81,65.81 J1.1@9.81,74.1
VIN_2: C4.2 J3.1 pad.7@36.04,68.3 U2.1 | length 5.8
  Top Layer w1.6: pad.7@36.04,68.3 J3.1@36.04,74.1
VIN_3: C7.2 J5.2 pad.9@57.78,68.3 R8.2 U3.2 | length 19.5
  Top Layer w0.7: R8.2@63.15,58.8 v1(64.5,58.8)
  Top Layer w1.5: J5.2@57.78,74.18 J5.2@57.8,74.2
  Top Layer w1.6: pad.9@57.78,68.3 J5.2@57.78,74.18
  Bottom Layer w0.7: pad.9@57.78,68.3 57.78,65.52 v1(64.5,58.8)
VIN_4: C20.2 J13.2 pad.9@7.72,9.9 R21.2 U9.2 | length 6.1
  Top Layer w1.5: pad.9@7.72,9.9 7.72,3.81 J13.2@7.73,3.8
VIN_5: C18.2 J12.2 pad.9@25.74,9.5 R20.1 U8.1 | length 11.1
  Top Layer w0.4: R20.1@23.9,18.35 24.75,18.35 25.5,19.1 27.6,19.1 27.95,19.45 U8.1@27.95,20.3
  Top Layer w1.5: J12.2@25.73,3.8 25.73,9.49 pad.9@25.74,9.5
  other v1: 32.011,16.478 33,16.5 34,16.5
VIN_6: C15.2 J10.3 pad.9@45.02,9.5 R15.1 U7.1 U7.2 | length 5.7
  Top Layer w1.6: J10.3@45,3.8 J10.3@45.02,3.82
  Bottom Layer w1.6: J10.3@45.02,3.82 pad.9@45.02,9.5
  other v1: 37.9,21.5 38.9,21.5
VIN_7: C13.2 J9.2 pad.9@61.74,9.6 R13.1 U6.3 | length 17.8
  Top Layer w0.9: R13.1@58.3,20.15 58.3,14.5 61.74,11.06 pad.9@61.74,9.6
  Top Layer w1.6: J9.2@61.73,3.8 61.74,3.81 pad.9@61.74,9.6
VIN_8: C11.2 J8.1 J8.2 pad.9@75.92,9.6 pad.9@78.46,9.6 U5.1 | length 19.8
  Top Layer w0.9: C11.2@76.55,16.3 U5.1@78.7,16.3 78.7,13.25 78.45,13 78.45,9.61 pad.9@78.46,9.6
  Top Layer w1.6: J8.1@75.92,3.8 J8.2@78.46,3.8 pad.9@78.46,9.6 pad.9@75.92,9.6
VIN_9: C9.2 J7.1 J7.2 pad.7@84.58,68.4 pad.9@82.04,68.4 U4.1 | length 19.8
  Top Layer w0.9: U4.1@81.8,61.7 C9.2@83.95,61.7
  Top Layer w1: U4.1@81.8,61.7 81.8,66 82,66.2 82,68.36 pad.9@82.04,68.4
  Top Layer w1.6: pad.7@84.58,68.4 pad.9@82.04,68.4 J7.2@82.04,74.2 J7.1@84.58,74.2
VOUT1_1: C2.2 J1.4 pad.7@2.2,65.8 U1.8 | length 8.3
  Top Layer w1.6: J1.4@2.19,74.1 2.2,74.09 pad.7@2.2,65.8
VOUT2_1: C3.2 J1.3 pad.8@4.74,65.8 R2.1 R3.1 U1.5 | length 19.9
  Top Layer w0.5: R3.1@14.35,60.7 v1(14.35,58.95) 16.1,57.2 R2.1@16.95,57.2
  Top Layer w1.6: J1.3@4.73,74.1 4.74,74.09 pad.8@4.74,65.8
  Bottom Layer w0.5: 8.6,57 12.4,57 v1(14.35,58.95)
  other v1: 7.8,55.3 7.8,56.3
VOUT_2: C5.2 J3.3 pad.7@30.96,68.3 R4.1 U2.8 | length 5.8
  Top Layer w1.6: pad.7@30.96,68.3 J3.3@30.96,74.1
  other v1: 27,52.8 27,54.2
VOUT_3: C8.2 J5.4 pad.7@52.7,68.3 R9.1 U3.4
VOUT_4: C21.2 J13.4 pad.7@12.8,9.9 U9.4 | length 6.1
  Top Layer w1.5: pad.7@12.8,9.9 12.8,3.81 J13.4@12.81,3.8
VOUT_5: C19.2 J12.4 pad.7@30.82,9.5 U8.5 | length 5.7
  Top Layer w1.5: J12.4@30.81,3.8 30.81,9.49 pad.7@30.82,9.5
